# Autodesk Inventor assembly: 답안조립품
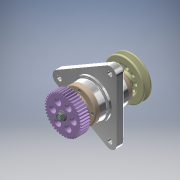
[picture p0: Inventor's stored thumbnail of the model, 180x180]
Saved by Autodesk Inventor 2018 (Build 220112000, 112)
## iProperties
Created: 2023-04
Part Number: 답안조립품
Material: 일반
Document SubType Name: Assembly
Designer: home
Author: home
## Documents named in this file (11)
- C:\Users\home\Desktop\730407V1003\답안조립품.iam
- C:\Users\home\Desktop\730407V1003\6각 플랜지 너트 M10.ipt
- C:\Users\home\Desktop\730407V1003\v-벨트풀리.ipt
- C:\Users\home\Desktop\730407V1003\묻힘키 5x5x16.ipt
- C:\Users\home\Desktop\730407V1003\베어링 6204.ipt
- C:\Users\home\Desktop\730407V1003\본체.ipt
- C:\Users\home\Desktop\730407V1003\볼트 M4 x 12.ipt
- C:\Users\home\Desktop\730407V1003\스퍼기어.ipt
- C:\Users\home\Desktop\730407V1003\오일 실 20 32 8.ipt
- C:\Users\home\Desktop\730407V1003\축.ipt
- C:\Users\home\Desktop\730407V1003\커버.ipt
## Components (3 placed, 2 different names)
1. 6각 플랜지 너트 M10:1
2. v-벨트풀리:1
3. 6각 플랜지 너트 M10:2
